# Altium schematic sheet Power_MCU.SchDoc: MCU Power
size A4; Date: Not used; ApprovedBy: Not used; CheckedBy: Not used; Author: Not used; CompanyName: STMicroelectronics; DrawnBy: Not used; Engineer: Not used; Organization: Not used; Address1: Not used; Address2: Not used; Address3: Not used; Address4: Not used; DocumentNumber: Not used; Revision: Not used; SheetNumber: 21; SheetTotal: 23
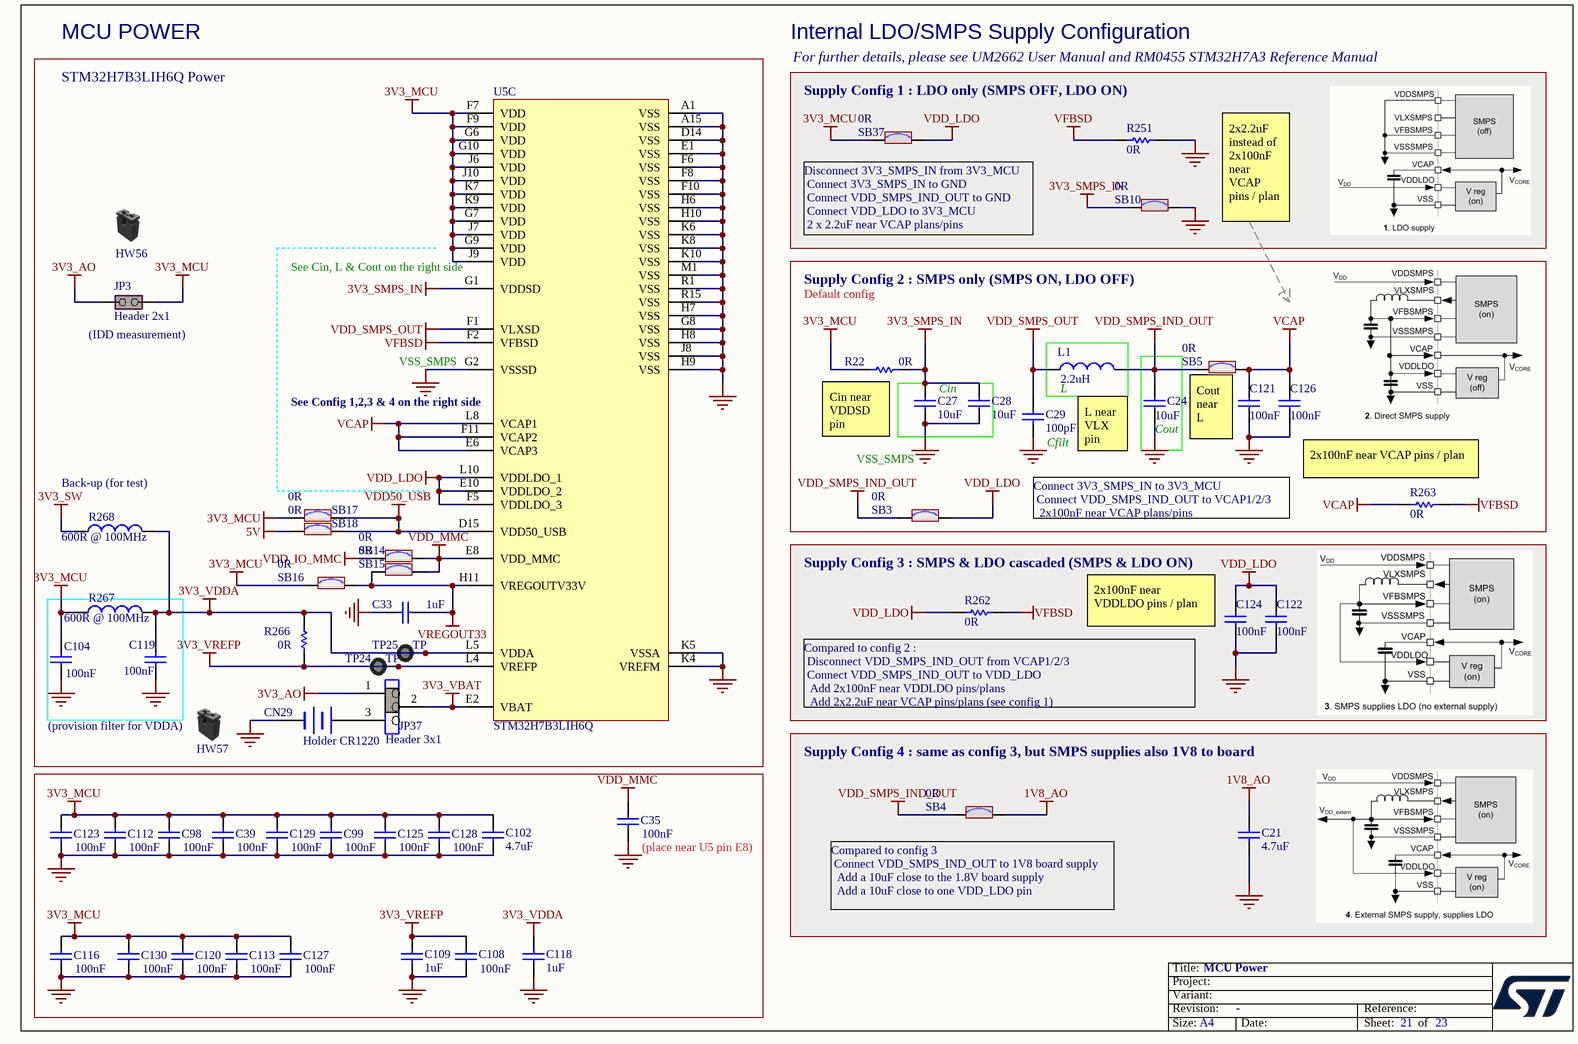
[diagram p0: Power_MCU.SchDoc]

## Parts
C21  value 4.7uF  [C0603]  (hidden comment: Capacitor)
C24  value 10uF  [C0603]  (hidden comment: Capacitor)
C27  value 10uF  [C0402]  (hidden comment: Capacitor)
C28  value 10uF  [C0402]  (hidden comment: Capacitor)
C29  value 100pF  [C0402]  (hidden comment: Capacitor)
C33  value 1uF  [C0603]  (hidden comment: Capacitor)
C35  value 100nF  [C0402]  (hidden comment: Capacitor)
C39  value 100nF  [C0402]  (hidden comment: Capacitor)
C98  value 100nF  [C0402]  (hidden comment: Capacitor)
C99  value 100nF  [C0402]  (hidden comment: Capacitor)
C102  value 4.7uF  [C0603]  (hidden comment: Capacitor)
C104  value 100nF  [C0402]  (hidden comment: Capacitor)
C108  value 100nF  [C0402]  (hidden comment: Capacitor)
C109  value 1uF  [C0402]  (hidden comment: Capacitor)
C112  value 100nF  [C0402]  (hidden comment: Capacitor)
C113  value 100nF  [C0402]  (hidden comment: Capacitor)
C116  value 100nF  [C0402]  (hidden comment: Capacitor)
C118  value 1uF  [C0402]  (hidden comment: Capacitor)
C119  value 100nF  [C0402]  (hidden comment: Capacitor)
C120  value 100nF  [C0402]  (hidden comment: Capacitor)
C121  value 100nF  [C0402]  (hidden comment: Capacitor)
C122  value 100nF  [C0402]  (hidden comment: Capacitor)
C123  value 100nF  [C0402]  (hidden comment: Capacitor)
C124  value 100nF  [C0402]  (hidden comment: Capacitor)
C125  value 100nF  [C0402]  (hidden comment: Capacitor)
C126  value 100nF  [C0402]  (hidden comment: Capacitor)
C127  value 100nF  [C0402]  (hidden comment: Capacitor)
C128  value 100nF  [C0402]  (hidden comment: Capacitor)
C129  value 100nF  [C0402]  (hidden comment: Capacitor)
C130  value 100nF  [C0402]  (hidden comment: Capacitor)
CN29  value Holder CR1220  [BAT_HARWIN_S8411-45R_SMD_2P]  (hidden comment: BATTERY HOLDER)
HW56  Shunt Black 2.54mm  (value not drawn)  (mechanical)
HW57  Shunt Black 2.54mm  (value not drawn)  (mechanical)
JP3  value Header 2x1  [CON_SAMTEC_TSW-102-07-G-S]  (hidden comment: Jumper_Header 2x1 Fitted)
JP37  value Header 3x1  [CON_SAMTEC_TSW-103-07-F-S]  (hidden comment: Jumper_Header 3x1 Fitted 1-2)
L1  value 2.2uH  [L0805_H0P9]  (hidden comment: Inductor)
R22  value 0R  [R0603]  (hidden comment: Resistor)
R251  value 0R  [R0402]  (hidden comment: Resistor)
R262  value 0R  [R0402]  (hidden comment: Resistor)
R263  value 0R  [R0402]  (hidden comment: Resistor)
R266  value 0R  [R0603]  (hidden comment: Resistor)
R267  value 600R @ 100MHz  [L0603]  (hidden comment: BEAD)
R268  value 600R @ 100MHz  [L0603]  (hidden comment: BEAD)
SB3  value 0R  [SOLDER-BRIDGE_R0603-0R]  (hidden comment: SB_ON)
SB4  value 0R  [SOLDER-BRIDGE_R0603-0R]  (hidden comment: SB_ON)
SB5  value 0R  [SOLDER-BRIDGE_R0603-0R]  (hidden comment: SB_ON)
SB10  value 0R  [SOLDER-BRIDGE_R0603-0R]  (hidden comment: SB_ON)
SB14  value 0R  [SOLDER-BRIDGE_R0603-0R]  (hidden comment: SB_ON)
SB15  value 0R  [SOLDER-BRIDGE_R0603-0R]  (hidden comment: SB_ON)
SB16  value 0R  [SOLDER-BRIDGE_R0603-0R]  (hidden comment: SB_ON)
SB17  value 0R  [SOLDER-BRIDGE_R0603-0R]  (hidden comment: SB_ON)
SB18  value 0R  [SOLDER-BRIDGE_R0603-0R]  (hidden comment: SB_ON)
SB37  value 0R  [SOLDER-BRIDGE_R0603-0R]  (hidden comment: SB_ON)
TP24  value TP  [TP_PTH_1MM_2MM]  (hidden comment: Test_Point_PTH_1mm_2mm)  (no BOM)
TP25  value TP  [TP_PTH_1MM_2MM]  (hidden comment: Test_Point_PTH_1mm_2mm)  (no BOM)
U5  value STM32H7B3LIH6Q  [ICC_TFBGA225_13X13_STM32H7B3NIH6Q_P080__SOCKET_IRONWOOD_CS1222291MF_REV-A_WITHOUT-3D-SOCKET]  (hidden comment: STM32H7B3NIH6Q)  (part C of 3)

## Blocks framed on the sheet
MCU POWER: C33 C104 C119 CN29 HW56 HW57 JP3 JP37 R266-R268 SB14-SB18 TP24 TP25 U5
Supply Config 1 : LDO only (SMPS OFF, LDO ON): R251 SB10 SB37
Supply Config 2 : SMPS only (SMPS ON, LDO OFF): C29 C121 C126 R22 R263 SB3 SB5
L: L1
Cin: C27 C28
Cout: C24
Supply Config 3 : SMPS & LDO cascaded (SMPS & LDO ON): C122 C124 R262
(place near U5 pin E8): C35 C39 C98 C99 C102 C108 C109 C112 C113 C116 C118 C120 C123 C125 C127-C130

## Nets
1V8_AO: C21.2 SB4.2
3V3_AO: JP3.1(COMMON) JP37.1
3V3_MCU: C39.1 C98.1 C99.1 C102.2 C104.1 C112.1 C113.1 C116.1 C120.1 C123.1 C125.1 C127.1 C128.1 C129.1 C130.1 JP3.2(NO) R22.2 R267.1 SB16.1 SB17.2 SB37.2 U5.F7(VDD) U5.F9(VDD) U5.G6(VDD) U5.G7(VDD) U5.G9(VDD) U5.G10(VDD) U5.J6(VDD) U5.J7(VDD) U5.J9(VDD) U5.J10(VDD) U5.K7(VDD) U5.K9(VDD)
3V3_SMPS_IN: C27.2 C28.2 R22.1 SB10.2 U5.G1(VDDSD)
3V3_SW: R268.1
3V3_VBAT: JP37.2 U5.E2(VBAT)
3V3_VDDA: C118.2 C119.1 R266.1 R267.2 R268.2 TP25.1 U5.L5(VDDA)
3V3_VREFP: C108.2 C109.2 R266.2 TP24.1 U5.L4(VREFP)
5V: SB18.2
GND: C21.1 C24.1 C27.1 C28.1 C29.1 C33.2 C35.2 C39.2 C98.2 C99.2 C102.1 C104.2 C108.1 C109.1 C112.2 C113.2 C116.2 C118.1 C119.2 C120.2 C121.2 C122.2 C123.2 C124.2 C125.2 C126.2 C127.2 C128.2 C129.2 C130.2 CN29.2(-) R251.2 SB10.1 U5.A1(VSS) U5.A15(VSS) U5.D14(VSS) U5.E1(VSS) U5.F6(VSS) U5.F8(VSS) U5.F10(VSS) U5.G2(VSSSD) U5.G8(VSS) U5.H6(VSS) U5.H7(VSS) U5.H8(VSS) U5.H9(VSS) U5.H10(VSS) U5.J8(VSS) U5.K4(VREFM) U5.K5(VSSA) U5.K6(VSS) U5.K8(VSS) U5.K10(VSS) U5.M1(VSS) U5.R1(VSS) U5.R15(VSS)
VCAP: C121.1 C126.1 R263.1 SB5.1 U5.E6(VCAP3) U5.F11(VCAP2) U5.L8(VCAP1)
VDD50_USB: SB17.1 SB18.1 U5.D15(VDD50_USB)
VDD_IO_MMC: SB14.1
VDD_LDO: C122.1 C124.1 R262.1 SB3.1 SB37.1 U5.E10(VDDLDO_2) U5.F5(VDDLDO_3) U5.L10(VDDLDO_1)
VDD_MMC: C35.1 SB14.2 SB15.1 U5.E8(VDD_MMC)
VDD_SMPS_IND_OUT: C24.2 L1.2 SB3.2 SB4.1 SB5.2
VDD_SMPS_OUT: C29.2 L1.1 U5.F1(VLXSD)
VFBSD: R251.1 R262.2 R263.2 U5.F2(VFBSD)
VREGOUT33: C33.1 SB15.2 SB16.2 U5.H11(VREGOUTV33V)
NetCN29_1: CN29.1(+) JP37.3

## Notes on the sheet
- Internal LDO/SMPS Supply Configuration
- STM32H7B3LIH6Q Power
- For further details, please see UM2662 User Manual and RM0455 STM32H7A3 Reference Manual
- (near SB37) Disconnect 3V3_SMPS_IN from 3V3_MCU
  Connect 3V3_SMPS_IN to GND
  Connect VDD_SMPS_IND_OUT to GND
  Connect VDD_LDO to 3V3_MCU
  2 x 2.2uF near VCAP plans/pins
- 2x2.2uF instead of 2x100nF near VCAP pins / plan
- (near U5) See Cin, L & Cout on the right side
- Default config
- (near JP3) (IDD measurement)
- (near U5) VSS_SMPS
- (near U5) See Config 1,2,3 & 4 on the right side
- (near R22) Cin near VDDSD pin
- (near C29) Cfilt
- L near VLX pin
- (near SB5) Cout near L
- (near R268) Back-up (for test)
- VSS_SMPS
- Connect 3V3_SMPS_IN to 3V3_MCU
  Connect VDD_SMPS_IND_OUT to VCAP1/2/3
  2x100nF near VCAP plans/pins
- 2x100nF near VCAP pins / plan
- (near C124) 2x100nF near VDDLDO pins / plan
- Compared to config 2 :
  Disconnect VDD_SMPS_IND_OUT from VCAP1/2/3
  Connect VDD_SMPS_IND_OUT to VDD_LDO
  Add 2x100nF near VDDLDO pins/plans
  Add 2x2.2uF near VCAP pins/plans (see config 1)
- (near HW57) (provision filter for VDDA)
- Supply Config 4 : same as config 3, but SMPS supplies also 1V8 to board
- (near SB4) Compared to config 3
  Connect VDD_SMPS_IND_OUT to 1V8 board supply
  Add a 10uF close to the 1.8V board supply
  Add a 10uF close to one VDD_LDO pin

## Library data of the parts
C21 C102 = MCD-04044: Capacitor, MLCC, 4.7uF, 10V, X5R, 20%, 0603, T=0.8mm; Manufacturer_Part_Number: C0603C475M8PAC7040; Manufacturer: KEMET CORPORATION; Part_Preference: Recommended; Component_Country_Of_Origin: Mexico; ShowFields: YES; ID: 6160
C24 = MCD-01341: Capacitor, MLCC, 10uF, 6V3, X5R, 20%, 0603, T=0,8mm; Manufacturer_Part_Number: GRM188R60J106ME47D; Manufacturer: MURATA; Part_Preference: Recommended; Provided_By: SUBCO; ECCN_US: EAR99; ECCN_EU: NEC; Component_Country_Of_Origin: Japan°°; ID: 3441; ShowFields: YES
C27 C28 = MCD-01716: Capacitor, MLCC, 10uF, 6V3, X5R, 20%, 0402, T=0.5mm; Manufacturer_Part_Number: CC0402MRX5R5BB106; Manufacturer: YAGEO; Part_Preference: Recommended; Provided_By: SUBCO; Component_Country_Of_Origin: China; ID: 3816; ShowFields: YES
C29 = MCD-00205: Capacitor, MLCC, 100pF, 50V, NPO, 5%, 0402, T=0,5mm; Manufacturer_Part_Number: CC0402JRNPO9BN101; Manufacturer: YAGEO; Part_Preference: Recommended; Provided_By: SUBCO; ECCN_US: EAR99; ECCN_EU: NEC; Component_Country_Of_Origin: China; ID: 2658; ShowFields: YES
C33 = MCD-00010: Capacitor, MLCC, 1uF, 16V, X5R, 10%, 0603, T=0,8mm; Manufacturer_Part_Number: CC0603KRX5R7BB105; Manufacturer: YAGEO; Part_Preference: Recommended; Provided_By: SUBCO; ECCN_US: EAR99; ECCN_EU: NEC; Component_Country_Of_Origin: China; ID: 2470; Order_Code_RS: 2370680; ShowFields: YES
C35 C39 C98 C99 C104 C108 C112 C113 C116 C119-C130 = MCD-00006: Capacitor, MLCC, 100nF, 16V, X7R, 10%, 0402, T=0.5mm; Manufacturer_Part_Number: CC0402KRX7R7BB104; Manufacturer: YAGEO; Alternate_Manufacturer_Part_Number: GCM155R71C104KA55D; Alternate_Manufacturer: MURATA; Part_Preference: Recommended; Partial_Alternate_Internal_Part_Number: MCD-03299; Provided_By: SUBCO; ECCN_US: EAR99; ECCN_EU: NEC; Component_Country_Of_Origin: China; ID: 2474; Order_Code_RS: 9402047; ShowFields: YES
C109 C118 = MCD-00095: Capacitor, MLCC, 1uF, 6V3, X5R, 10%, 0402, T=0,5mm; Manufacturer_Part_Number: GRM155R61E105KA12; Manufacturer: MURATA; Alternate_Manufacturer_Part_Number: GRM155R60J105KE19; Part_Preference: Recommended; Provided_By: SUBCO; ECCN_US: EAR99; ECCN_EU: NEC; Component_Country_Of_Origin: Japan°°; ID: 2772; Order_Code_RS: 2218855; ShowFields: YES
CN29 = MCD-00558: Battery Coin Cell holder, CR1220_12mm, Height 4.25mm; Part_Type: Connector; Manufacturer_Part_Number: S8411-45R; Manufacturer: HARWIN; Part_Preference: Recommended; Provided_By: SUBCO; Component_Country_Of_Origin: Taiwan; ID: 3187; ShowFields: YES
HW56 HW57 = MCD-00043: SHUNT 2.54mm BLACK; Part_Type: Misc; Manufacturer: SAMTEC; Alternate_Manufacturer_Part_Number: 316102S111A; Alternate_Manufacturer: JIUBABA; Full_Alternate_Internal_Part_Number: MCD-02388; Manufacturer_HQ_COO: Unknown; Part_Preference: Recommended; Partial_Alternate_Internal_Part_Number: MCD-01849; Value: SNT-100-BK-G; Provided_By: SUBCO; Alternate_EMS: A; Component_Country_Of_Origin: China, Costa Rica, Malaysia, USA, Vietnam; ID: 2551; Order_Code_RS: 158-7784; ShowFields: YES
JP3 = MCD-00683: Header, 2x1, 2,54mm, VR, TH, Height 5.84mm/2.54mm - Shunt Fitted by default; Part_Type: Connector; Manufacturer_Part_Number: TSW-102-07-G-S; Manufacturer: SAMTEC; Alternate_Manufacturer_Part_Number: 313102S111116; Alternate_Manufacturer: LIANYI; Full_Alternate_Internal_Part_Number: MCD-02389; Part_Preference: Recommended; Partial_Alternate_Internal_Part_Number: MCD-02957, MCD-03720; Provided_By: SUBCO; Component_Country_Of_Origin: China, Costa Rica, Malaysia, USA, Vietnam; ID: 3057; Order_Code_RS: 155-5312; ShowFields: YES
JP37 = MCD-00684: Header, 3x1, 2,54mm, VR, TH, Height 5.84mm/2.54mm - Shunt Fitted 1-2 by default; Part_Type: Connector; Manufacturer_Part_Number: TSW-103-07-F-S; Manufacturer: SAMTEC; Part_Preference: Recommended; Partial_Alternate_Internal_Part_Number: MCD-03595, MCD-03723; Provided_By: SUBCO; Alternate_EMS: A; Component_Country_Of_Origin: China, Costa Rica, Malaysia, USA, Vietnam; ID: 3059; Order_Code_RS: 161-2248; ShowFields: YES
L1 = MCD-01340: Inductor, 2.2uH, 20%, Isat 1.2A, DCR 0.228Ohm, 0805; Manufacturer_Part_Number: DFE201210U-2R2M=P2; Manufacturer: MURATA; Part_Preference: Recommended; Provided_By: SUBCO; Component_Country_Of_Origin: Japan°°; ID: 3440; ShowFields: YES
R22 R266 = MCD-00056: Resistor,0R,0603,5%,1/10W; Manufacturer_Part_Number: RC0603JR-070RL; Manufacturer: YAGEO; Part_Preference: Recommended; Provided_By: SUBCO; ECCN_US: EAR99; ECCN_EU: NEC; Component_Country_Of_Origin: China; ID: 2536; Order_Code_RS: 9233130RL; ShowFields: YES
R251 R262 R263 = MCD-00052: Resistor,0R,0402,5%,1/16W; Manufacturer_Part_Number: RC0402JR-070RL; Manufacturer: YAGEO; Part_Preference: Recommended; Provided_By: SUBCO; ECCN_US: EAR99; ECCN_EU: NEC; Component_Country_Of_Origin: China; ID: 2540; Order_Code_RS: 9232516RL; ShowFields: YES
R267 R268 = MCD-00047: SMD Chip ferrite bead, 600R@100MHz +/-25%, 350mA, 500mohm DC, 0603, T=0.8mm; Part_Type: Inductor; Manufacturer_Part_Number: FCM1608KF-601T03; Manufacturer: TAI-TECH; Part_Preference: Recommended; Partial_Alternate_Internal_Part_Number: MCD-02959; Provided_By: SUBCO; Component_Country_Of_Origin: Unknown; ID: 2546; ShowFields: YES
SB3-SB5 SB10 SB14-SB18 SB37 = MCD-00071: Solder Bridge ON; Part_Type: Resistor; Manufacturer_Part_Number: RC0603JR-070RL; Manufacturer: YAGEO; Manufacturer_HQ_COO: Unknown; Part_Preference: Recommended; Provided_By: SUBCO; Component_Country_Of_Origin: China; ID: 2521; Order_Code_RS: 199-5647; ShowFields: YES
TP24 TP25 = MCD-01506: Test Point trought hole 1mm/2mm; Part_Type: Misc; Part_Preference: Recommended; Component_Country_Of_Origin: Unknown; ID: 3606; ShowFields: YES
U5 = MCD-01929: STM32H7B3LIH6Q (crypto),TFBGA 225, 13x13 0.8; Part_Type: IC; Manufacturer: STMICROELECTRONICS; BMS_Part_Number: 9175358; Manufacturer_HQ_COO: EU; Part_Preference: Recommended; ECCN_US: 5A992C; ECCN_EU: 5A002A4; Provided_By: SUBCO with ST control; Component_Country_Of_Origin: Philippines; ID: 4029; Order_Code_RS: 201-4447; ShowFields: YES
